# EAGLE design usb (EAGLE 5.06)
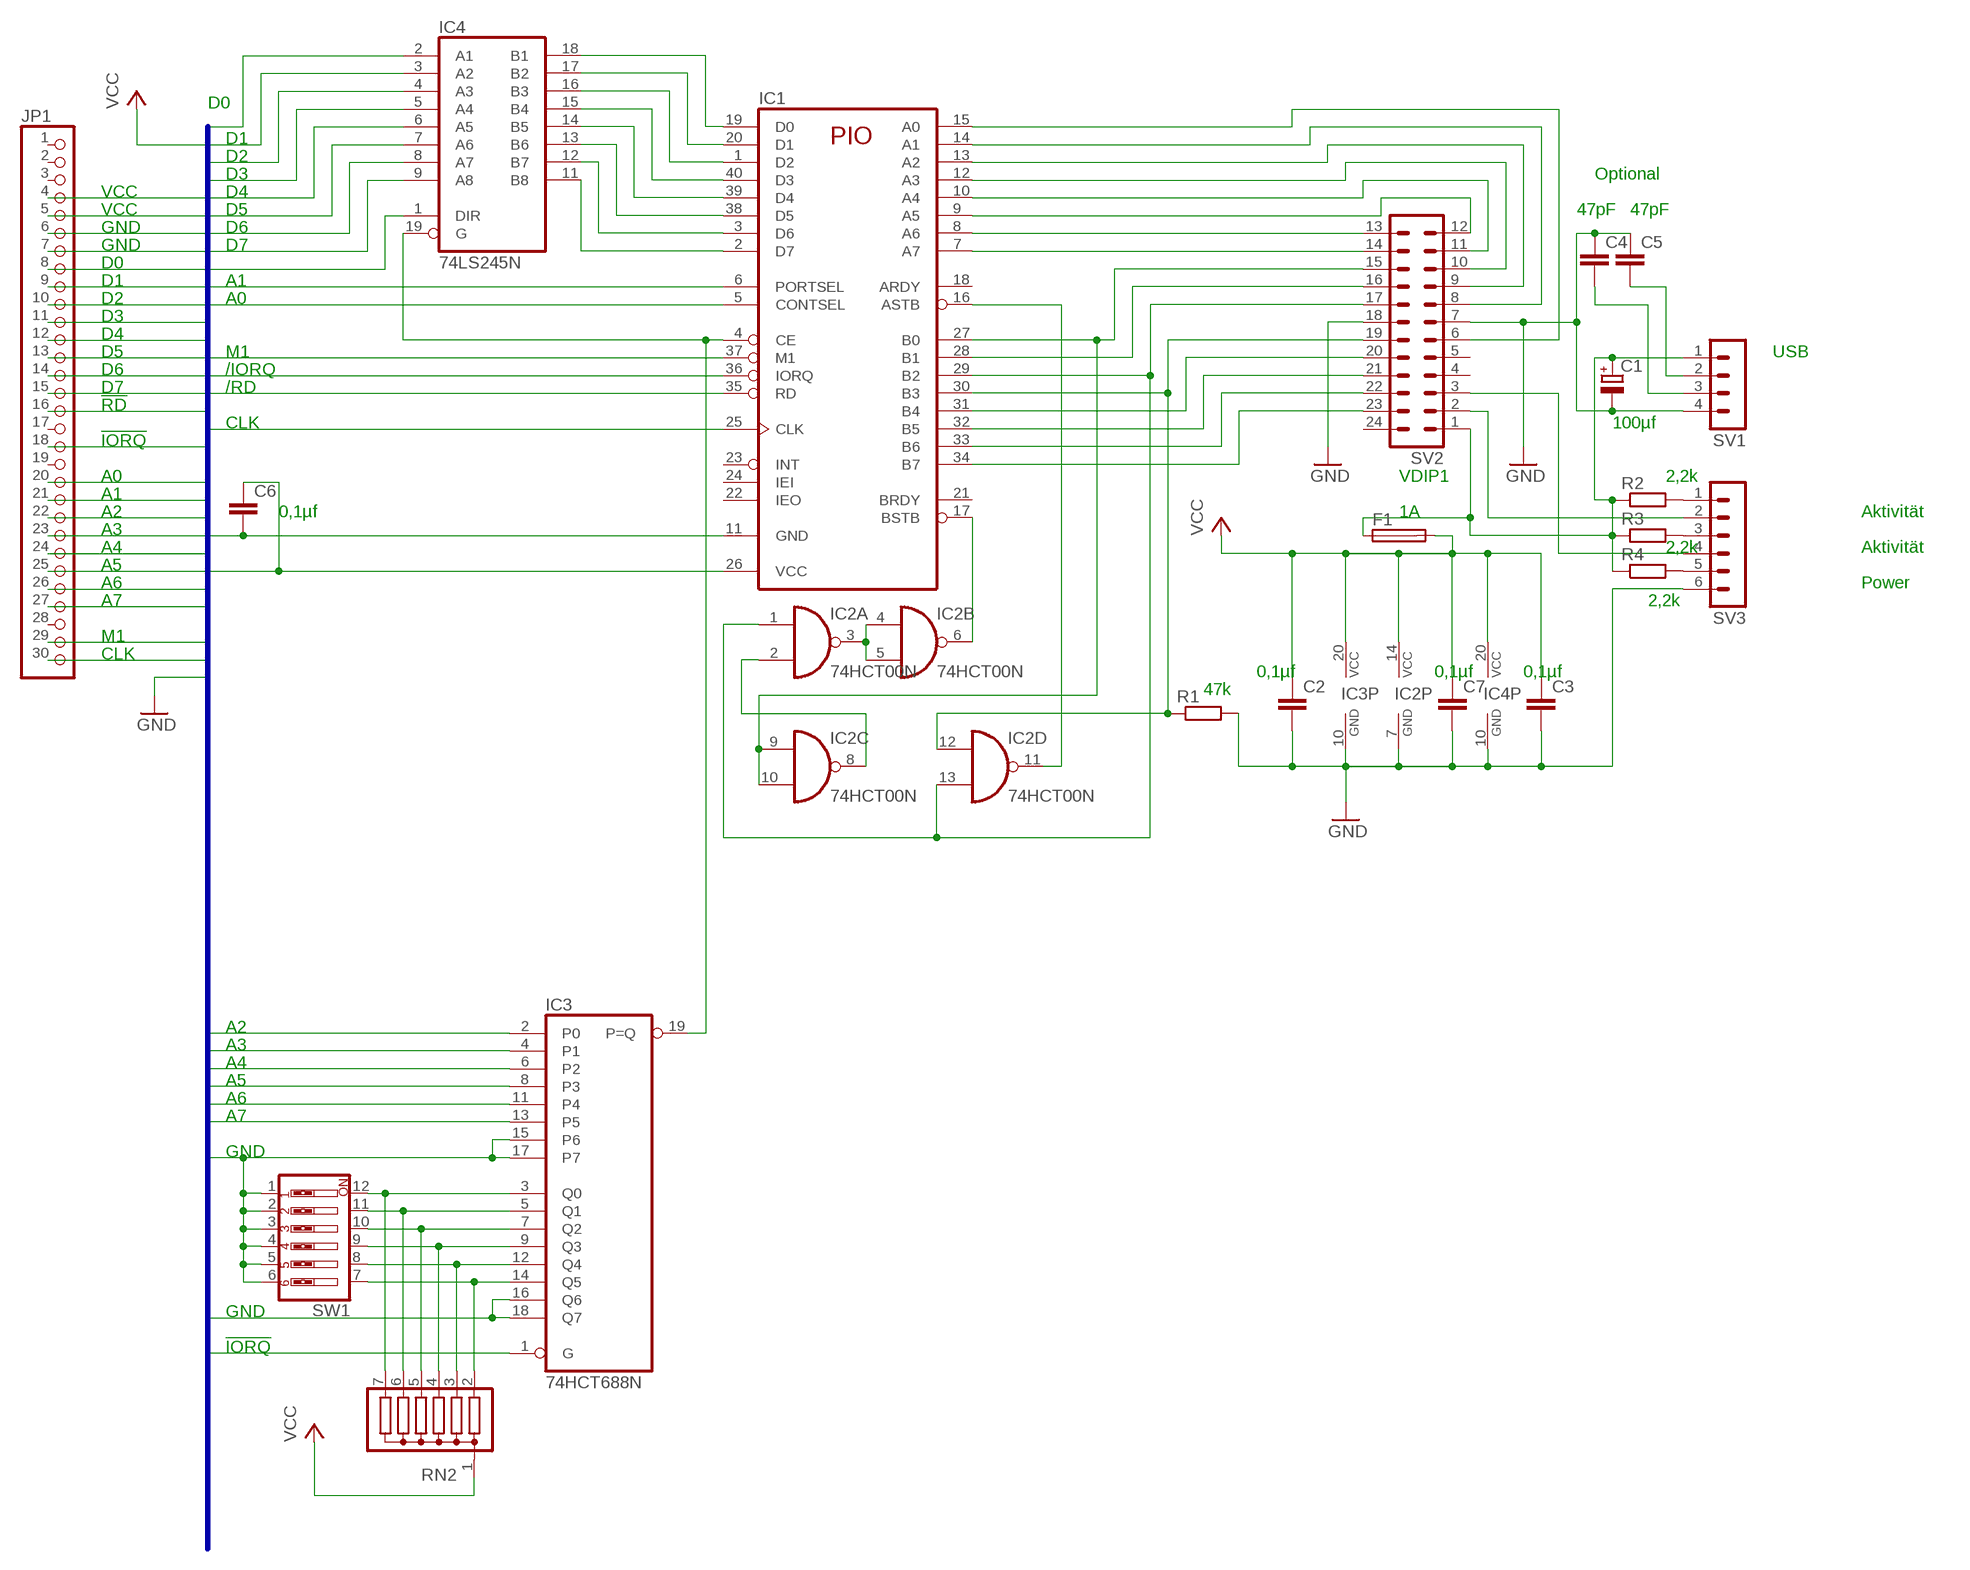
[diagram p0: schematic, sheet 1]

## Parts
C1  CPOL-EUE3.5-10  [E3,5-10]
C2  C-EU025-050X050  [C025-050X050]
C3  C-EU025-050X050  [C025-050X050]
C4  C-EU025-050X050  [C025-050X050]
C5  C-EU025-050X050  [C025-050X050]
C6  C-EU025-050X050  [C025-050X050]
C7  C-EU025-050X050  [C025-050X050]
F1  SH22,5  [SH22,5]
IC1  Z80PIO  [DIL40]
IC2  74HCT00N  [DIL14]
IC3  74HCT688N  [DIL20]
IC4  74LS245N  [DIL20]
JP1  PINHD-1X30  [1X30]
R1  R-EU_0207/15  [0207/15]
R2  R-EU_0207/15  [0207/15]
R3  R-EU_0207/15  [0207/15]
R4  R-EU_0207/15  [0207/15]
RN2  G06R  [SIL7]
SV1  MA04-1  [MA04-1]
SV2  IC24P  [IC24P]
SV3  MA06-1  [MA06-1]
SW1  SW_DIP-6  [EDG-06]

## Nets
!IORQ: IC1.36(IORQ) IC3.1(G) JP1.18
!RD: IC1.35(RD) IC4.1(DIR) JP1.16
A0: IC1.5(CONTSEL) JP1.20
A1: IC1.6(PORTSEL) JP1.21
A2: IC3.2(P0) JP1.22
A3: IC3.4(P1) JP1.23
A4: IC3.6(P2) JP1.24
A5: IC3.8(P3) JP1.25
A6: IC3.11(P4) JP1.26
A7: IC3.13(P5) JP1.27
CLK: IC1.25(CLK) JP1.30
D0: IC4.2(A1) JP1.8
D1: IC4.3(A2) JP1.9
D2: IC4.4(A3) JP1.10
D3: IC4.5(A4) JP1.11
D4: IC4.6(A5) JP1.12
D5: IC4.7(A6) JP1.13
D6: IC4.8(A7) JP1.14
D7: IC4.9(A8) JP1.15
GND [Power]: C1.- C2.2 C3.2 C4.1 C5.1 C6.2 C7.2 IC1.11(GND) IC2.7(P:GND) IC3.10(GND) IC3.15(P6) IC3.16(Q6) IC3.17(P7) IC3.18(Q7) IC4.10(GND) JP1.6 JP1.7 R1.2 SV1.4 SV2.7 SV2.18 SV3.6 SW1.1 SW1.2 SW1.3 SW1.4 SW1.5 SW1.6
M1: IC1.37(M1) JP1.29
N$1: IC1.4(CE) IC3.19(P=Q) IC4.19(G)
N$2: IC3.3(Q0) RN2.7 SW1.12
N$3: IC3.5(Q1) RN2.6 SW1.11
N$4: IC3.7(Q2) RN2.5 SW1.10
N$5: IC3.9(Q3) RN2.4 SW1.9
N$6: IC3.12(Q4) RN2.3 SW1.8
N$7: IC3.14(Q5) RN2.2 SW1.7
N$8: IC1.8(A6) SV2.13
N$9: IC1.9(A5) SV2.12
N$10: IC1.10(A4) SV2.11
N$11: IC1.12(A3) SV2.10
N$12: IC1.13(A2) SV2.9
N$13: IC1.14(A1) SV2.8
N$14: IC1.15(A0) SV2.6
N$15: IC1.7(A7) SV2.14
N$16: IC1.27(B0) IC2.9(C:I0) IC2.10(C:I1) SV2.15
N$17: IC1.28(B1) SV2.16
N$18: R2.2 SV3.1
N$19: IC1.30(B3) IC2.12(D:I0) R1.1 SV2.19
N$20: IC1.31(B4) SV2.20
N$21: IC1.32(B5) SV2.21
N$22: IC1.33(B6) SV2.22
N$23: IC1.34(B7) SV2.23
N$24: IC1.17(BSTB) IC2.6(B:O)
N$25: IC2.3(A:O) IC2.4(B:I0) IC2.5(B:I1)
N$26: IC1.16(ASTB) IC2.11(D:O)
N$27: IC1.29(B2) IC2.1(A:I0) IC2.13(D:I1) SV2.17
N$28: IC2.2(A:I1) IC2.8(C:O)
N$29: R3.2 SV3.3
N$30: R4.2 SV3.5
N$37 [Power]: C1.+ F1.1 R2.1 R3.1 R4.1 SV1.1 SV2.1
N$38: IC1.2(D7) IC4.11(B8)
N$39: SV2.2 SV3.2
N$40: SV2.3 SV3.4
N$41: C5.2 SV1.2
N$42: C4.2 SV1.3
N$43: IC1.3(D6) IC4.12(B7)
N$44: IC1.38(D5) IC4.13(B6)
N$45: IC1.39(D4) IC4.14(B5)
N$46: IC1.40(D3) IC4.15(B4)
N$47: IC1.1(D2) IC4.16(B3)
N$48: IC1.20(D1) IC4.17(B2)
N$49: IC1.19(D0) IC4.18(B1)
VCC [Power]: C2.1 C3.1 C6.1 C7.1 F1.2 IC1.26(VCC) IC2.14(P:VCC) IC3.20(VCC) IC4.20(VCC) JP1.4 JP1.5 RN2.1
Unconnected: IC1.18(ARDY) IC1.21(BRDY) IC1.22(IEO) IC1.23(INT) IC1.24(IEI) JP1.1 JP1.2 JP1.3 JP1.17 JP1.19 JP1.28 SV2.4 SV2.5 SV2.24

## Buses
D[0..7],A[0..7],!WR,!RD,!IORQ,GND,VCC,CLK,M1,RESET,!INT

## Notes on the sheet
- D0
- D1
- D2
- D3 | Optional
- VCC | D4
- VCC | D5 | 47pF | 47pF
- GND | D6
- GND | D7
- D0
- D1 | A1
- D2 | A0
- D3
- D4
- D5 | M1 | USB
- D6 | /IORQ
- D7 | /RD
- !RD
- CLK | 100µf
- !IORQ
- A0 | VDIP1 | 2,2k
- A1
- A2 | 0,1µf | 1A | Aktivität
- A3
- A4 | 2,2k | Aktivität
- A5
- A6 | Power
- A7 | 2,2k
- M1
- CLK
- 0,1µf | 0,1µf | 0,1µf
- 47k
- A2
- A3
- A4
- A5
- A6
- A7
- GND
- GND
- !IORQ

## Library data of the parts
C1 = resistor:CPOL-EU: POLARIZED CAPACITOR, European symbol
C2-C7 = resistor:C-EU: CAPACITOR, European symbol
F1 = fuse:SH22,5: FUSE HOLDER
IC1 = zilog:Z80PIO: Z80 FAMILY DEVICE
IC2 = 74xx-eu:74*00: Quad 2-input NAND gate
IC3 = 74xx-eu:74*688: 8-bit MAGNITUDE/IDENTITY COMPARATOR, totem pole
IC4 = 74xx-eu:74*245: Octal BUS TRANSCEIVER, 3-state
JP1 = pinhead:PINHD-1X30: PIN HEADER
R1-R4 = rcl:R-EU_: RESISTOR, European symbol
RN2 = resistor-sil:G06R: SIL RESISTOR
SV1 = con-lstb:MA04-1: PIN HEADER
SV2 = con-dil:IC24P: DIL CABLE CONNECTOR
SV3 = con-lstb:MA06-1: PIN HEADER
SW1 = special:SW_DIP-6: DIP SWITCH

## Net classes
0 Default: width 0.55 mm, drill 0.4 mm, clearance 0.3 mm
1 Power: width 0.8 mm, drill 0.6 mm, clearance 0.3 mm

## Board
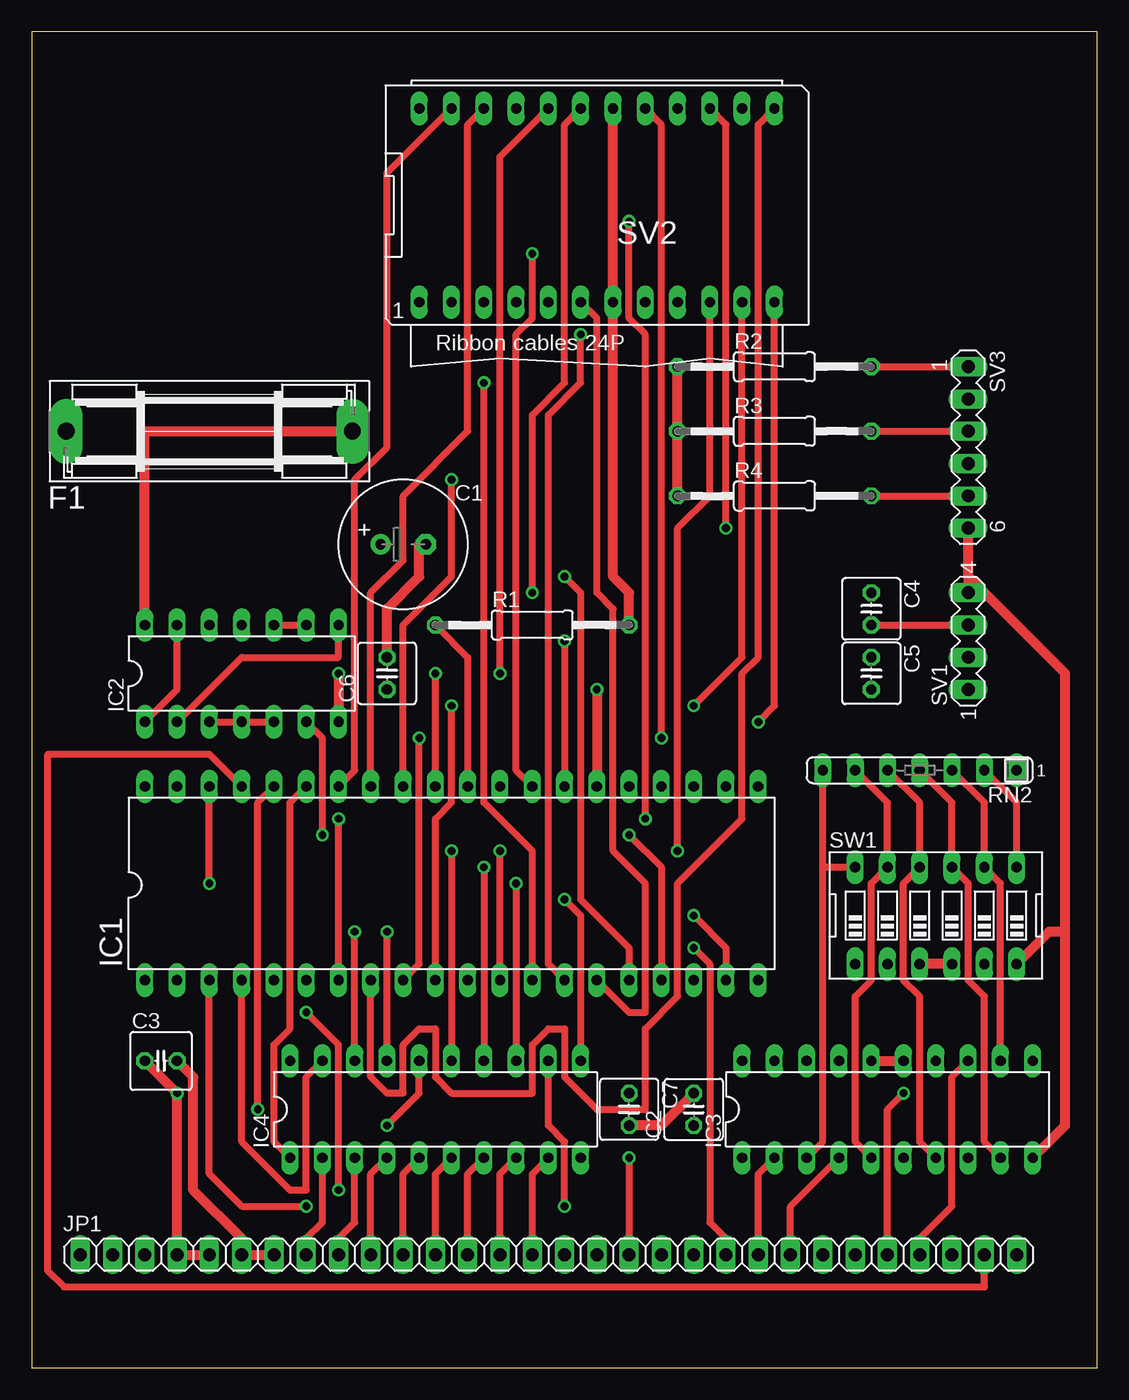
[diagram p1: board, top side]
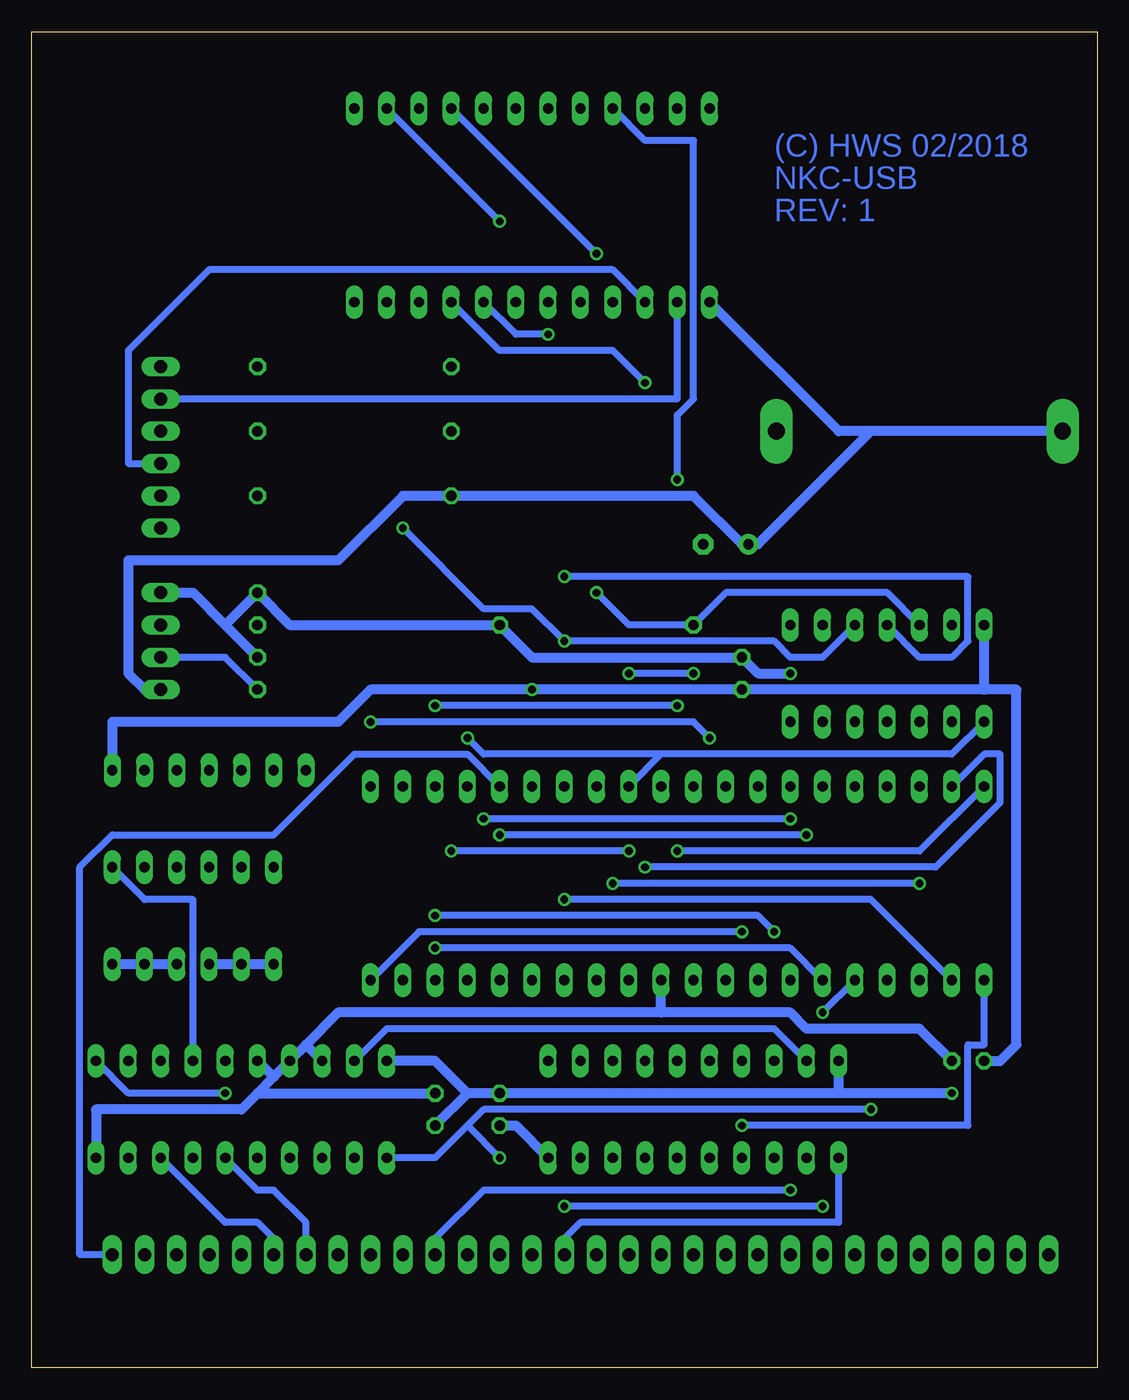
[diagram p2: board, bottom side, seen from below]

Size 83.8 x 105.08 mm. Coordinates in mm from the lower left corner, seen from the top.
Outline: 0,0 83.8,0 83.8,105.08 0,105.08 0,0
Copper layers (1*16): Top 0.035mm / dielectric 1.5mm / Bottom 0.035mm
Design rules "default": minimum track width 10mil, minimum drill 24mil, track to track 8mil, track to pad 8mil, pad to pad 8mil, via to via 8mil, smd to smd 8mil, copper to edge 40mil, drill to drill 8mil, minimum pad ring 10mil, minimum via ring 8mil, stop-mask expansion 4mil, vias tented up to drill 0mil, thermal gap 10mil

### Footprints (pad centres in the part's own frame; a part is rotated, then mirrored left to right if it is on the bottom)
E3,5-10 = drill 0.813 pad 1.6 round: + -1.778,0 | drill 0.813 pad 1.6 octagon: - 1.778,0
C025-050X050 = drill 0.813 octagon: 1 -1.27,0; 2 1.27,0
SH22,5 = drill 1.321 pad 2.54 long: 1 -11.252,0; 2 11.252,0
DIL40 = drill 0.813 long: 1 -24.13,-7.62; 2 -21.59,-7.62; 3 -19.05,-7.62; 4 -16.51,-7.62; 5 -13.97,-7.62; 6 -11.43,-7.62; 7 -8.89,-7.62; 8 -6.35,-7.62; 9 -3.81,-7.62; 10 -1.27,-7.62; 11 1.27,-7.62; 12 3.81,-7.62; 13 6.35,-7.62; 14 8.89,-7.62; 15 11.43,-7.62; 16 13.97,-7.62; 17 16.51,-7.62; 18 19.05,-7.62; 19 21.59,-7.62; 20 24.13,-7.62; 21 24.13,7.62; 22 21.59,7.62; 23 19.05,7.62; 24 16.51,7.62; 25 13.97,7.62; 26 11.43,7.62; 27 8.89,7.62; 28 6.35,7.62; 29 3.81,7.62; 30 1.27,7.62; 31 -1.27,7.62; 32 -3.81,7.62; 33 -6.35,7.62; 34 -8.89,7.62; 35 -11.43,7.62; 36 -13.97,7.62; 37 -16.51,7.62; 38 -19.05,7.62; 39 -21.59,7.62; 40 -24.13,7.62
DIL14 = drill 0.813 long: 1 -7.62,-3.81; 2 -5.08,-3.81; 3 -2.54,-3.81; 4 0,-3.81; 5 2.54,-3.81; 6 5.08,-3.81; 7 7.62,-3.81; 8 7.62,3.81; 9 5.08,3.81; 10 2.54,3.81; 11 0,3.81; 12 -2.54,3.81; 13 -5.08,3.81; 14 -7.62,3.81
DIL20 = drill 0.813 long: 1 -11.43,-3.81; 2 -8.89,-3.81; 3 -6.35,-3.81; 4 -3.81,-3.81; 5 -1.27,-3.81; 6 1.27,-3.81; 7 3.81,-3.81; 8 6.35,-3.81; 9 8.89,-3.81; 10 11.43,-3.81; 11 11.43,3.81; 12 8.89,3.81; 13 6.35,3.81; 14 3.81,3.81; 15 1.27,3.81; 16 -1.27,3.81; 17 -3.81,3.81; 18 -6.35,3.81; 19 -8.89,3.81; 20 -11.43,3.81
1X30 = drill 1.016 long: 1 -36.83,0; 2 -34.29,0; 3 -31.75,0; 4 -29.21,0; 5 -26.67,0; 6 -24.13,0; 7 -21.59,0; 8 -19.05,0; 9 -16.51,0; 10 -13.97,0; 11 -11.43,0; 12 -8.89,0; 13 -6.35,0; 14 -3.81,0; 15 -1.27,0; 16 1.27,0; 17 3.81,0; 18 6.35,0; 19 8.89,0; 20 11.43,0; 21 13.97,0; 22 16.51,0; 23 19.05,0; 24 21.59,0; 25 24.13,0; 26 26.67,0; 27 29.21,0; 28 31.75,0; 29 34.29,0; 30 36.83,0
0207/15 = drill 0.813 octagon: 1 -7.62,0; 2 7.62,0
SIL7 = drill 0.813 long: 1 -7.62,0; 2 -5.08,0; 3 -2.54,0; 4 0,0; 5 2.54,0; 6 5.08,0; 7 7.62,0
MA04-1 = drill 1.016 long: 1 -3.81,0; 2 -1.27,0; 3 1.27,0; 4 3.81,0
IC24P = drill 0.813 long: 1 -13.97,-7.62; 2 -11.43,-7.62; 3 -8.89,-7.62; 4 -6.35,-7.62; 5 -3.81,-7.62; 6 -1.27,-7.62; 7 1.27,-7.62; 8 3.81,-7.62; 9 6.35,-7.62; 10 8.89,-7.62; 11 11.43,-7.62; 12 13.97,-7.62; 13 13.97,7.62; 14 11.43,7.62; 15 8.89,7.62; 16 6.35,7.62; 17 3.81,7.62; 18 1.27,7.62; 19 -1.27,7.62; 20 -3.81,7.62; 21 -6.35,7.62; 22 -8.89,7.62; 23 -11.43,7.62; 24 -13.97,7.62
MA06-1 = drill 1.016 long: 1 -6.35,0; 2 -3.81,0; 3 -1.27,0; 4 1.27,0; 5 3.81,0; 6 6.35,0
EDG-06 = drill 0.813 long: 1 -6.35,-3.81; 2 -3.81,-3.81; 3 -1.27,-3.81; 4 1.27,-3.81; 5 3.81,-3.81; 6 6.35,-3.81; 7 6.35,3.81; 8 3.81,3.81; 9 1.27,3.81; 10 -1.27,3.81; 11 -3.81,3.81; 12 -6.35,3.81

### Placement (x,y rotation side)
C1  29.21,64.77 0 top
C2  52.07,20.32 90 top
C3  10.16,24.13 0 top
C4  66.04,59.69 270 top
C5  66.04,54.61 270 top
C6  27.94,54.61 90 top
C7  46.99,20.32 270 top
F1  13.97,73.66 0 top
IC1  33.02,38.1 0 top
IC2  16.51,54.61 0 top
IC3  67.31,20.32 0 top
IC4  31.75,20.32 0 top
JP1  40.64,8.89 0 top
R1  39.37,58.42 0 top
R2  58.42,78.74 0 top
R3  58.42,73.66 0 top
R4  58.42,68.58 0 top
RN2  69.85,46.99 180 top
SV1  73.66,57.15 90 top
SV2  44.45,91.44 0 top
SV3  73.66,72.39 270 top
SW1  71.12,35.56 0 top

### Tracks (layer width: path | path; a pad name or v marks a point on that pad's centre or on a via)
!IORQ  (via drill 0.61)
  Top 0.55: IC1.36 17.78,44.45 v17.78,20.32 | v46.99,16.51 JP1.18
  Bottom 0.55: v17.78,20.32 48.26,20.32 49.53,19.05 | 49.53,19.05 52.07,16.51 IC3.1 | 49.53,19.05 v46.99,16.51
!RD
  Top 0.55: IC1.35 20.32,44.45 20.32,26.67 19.05,25.4 19.05,17.78 IC4.1
  Bottom 0.55: IC4.1 20.32,11.43 40.64,11.43 41.91,10.16 JP1.16
A0  (via drill 0.61)
  Top 0.55: v21.59,27.94 24.13,25.4 v24.13,13.97
  Bottom 0.55: v21.59,27.94 IC1.5 | v24.13,13.97 48.26,13.97 52.07,10.16 JP1.20
A1  (via drill 0.61)
  Top 0.55: v52.07,33.02 53.34,31.75 53.34,11.43 54.61,10.16 JP1.21
  Bottom 0.55: IC1.6 24.13,33.02 v52.07,33.02
A2
  Top 0.55: IC3.2 57.15,15.24 JP1.22
A3
  Top 0.55: IC3.4 59.69,12.7 JP1.23
A4
  Bottom 0.55: IC3.6 66.04,13.97 64.77,13.97 62.23,11.43 JP1.24
A5
  Bottom 0.55: IC3.8 68.58,11.43 66.04,11.43 64.77,10.16 JP1.25
A6  (via drill 0.61)
  Top 0.55: v68.58,21.59 67.31,20.32 JP1.26
  Bottom 0.55: IC3.11 76.2,21.59 v68.58,21.59
A7
  Top 0.55: IC3.13 72.39,22.86 72.39,12.7 69.85,10.16 JP1.27
CLK
  Bottom 0.55: IC1.25 49.53,48.26 58.42,48.26 64.77,41.91 77.47,41.91 80.01,39.37 80.01,8.89 JP1.30
D0
  Top 0.55: IC4.2 22.86,11.43 21.59,10.16 JP1.8
D1
  Top 0.55: IC4.3 25.4,11.43 24.13,10.16 JP1.9
D2
  Top 0.55: IC4.4 26.67,15.24 JP1.10
D3
  Top 0.55: IC4.5 29.21,15.24 JP1.11
D4
  Top 0.55: IC4.6 31.75,15.24 JP1.12
D5
  Top 0.55: IC4.7 34.29,15.24 JP1.13
D6
  Top 0.55: IC4.8 36.83,15.24 JP1.14
D7
  Top 0.55: IC4.9 39.37,15.24 JP1.15
GND  (via drill 0.61)
  Top 0.8: C3.2 12.7,22.86 12.7,13.97 16.51,10.16 JP1.6 JP1.7 | C2.2 49.53,19.05 C7.2 | IC3.16 IC3.15 | 73.66,62.23 SV1.4 | 73.66,62.23 SV3.6 | SV2.18 SV2.7 45.72,62.23 46.99,60.96 R1.2 | v24.13,54.61 IC2.7 | C6.2 27.94,59.69 30.48,62.23 30.48,64.77 C1.- | IC3.10 81.28,19.05 81.28,34.29 | 81.28,34.29 81.28,54.61 73.66,62.23 | SW1.4 SW1.3 | SW1.6 80.01,34.29 81.28,34.29
  Bottom 0.8: IC4.10 45.72,19.05 C7.2 | 34.29,27.94 IC1.11 | 34.29,27.94 59.69,27.94 62.23,25.4 | 62.23,25.4 IC3.17 64.77,22.86 | 62.23,25.4 IC3.18 | IC3.10 78.74,20.32 67.31,20.32 66.04,21.59 | 64.77,22.86 66.04,21.59 | 64.77,22.86 IC3.16 | 66.04,21.59 C2.2 | C3.2 13.97,26.67 22.86,26.67 24.13,27.94 34.29,27.94 | 68.58,58.42 71.12,60.96 SV1.4 | 68.58,58.42 C5.1 | 68.58,58.42 C4.1 63.5,58.42 R1.2 44.45,55.88 C6.2 26.67,54.61 v24.13,54.61 | SW1.4 SW1.5 SW1.6 | SW1.3 SW1.2 SW1.1
M1
  Top 0.55: IC1.37 13.97,48.26 1.27,48.26 1.27,7.62 2.54,6.35 74.93,6.35 JP1.29
N$1
  Top 0.55: IC1.4 16.51,17.78 20.32,13.97 21.59,13.97 21.59,22.86 IC4.19
  Bottom 0.55: IC4.19 25.4,26.67 55.88,26.67 IC3.19
N$2
  Top 0.55: IC3.3 62.23,17.78 62.23,39.37 | 62.23,39.37 RN2.7 | 62.23,39.37 SW1.12
N$3
  Top 0.55: IC3.5 64.77,17.78 64.77,29.21 66.04,30.48 66.04,38.1 SW1.11 67.31,44.45 RN2.6
N$4
  Top 0.55: IC3.7 69.85,17.78 69.85,29.21 68.58,30.48 68.58,38.1 SW1.10 69.85,44.45 RN2.5
N$5
  Top 0.55: IC3.9 74.93,17.78 74.93,29.21 73.66,30.48 73.66,38.1 SW1.9 72.39,44.45 RN2.4
N$6
  Top 0.55: IC3.12 76.2,38.1 SW1.8 74.93,44.45 RN2.3
N$7
  Top 0.55: RN2.2 77.47,44.45 SW1.7
  Bottom 0.55: IC3.14 71.12,36.83 74.93,36.83 SW1.7
N$8
  Top 0.55: IC1.8 26.67,22.86 27.94,21.59 29.21,21.59 29.21,25.4 30.48,26.67 31.75,26.67 31.75,22.86 33.02,21.59 39.37,21.59 39.37,25.4 40.64,26.67 41.91,26.67 41.91,22.86 44.45,20.32 48.26,20.32 48.26,26.67 50.8,29.21 50.8,38.1 55.88,43.18 55.88,54.61 57.15,55.88 57.15,97.79 SV2.13
N$9  (via drill 0.61)
  Top 0.55: IC1.9 30.48,31.75 v30.48,49.53 | v57.15,50.8 58.42,52.07 SV2.12
  Bottom 0.55: v30.48,49.53 31.75,50.8 v57.15,50.8
N$10  (via drill 0.61)
  Top 0.55: IC1.10 31.75,43.18 33.02,44.45 v33.02,52.07 | v52.07,52.07 55.88,55.88 SV2.11
  Bottom 0.55: v33.02,52.07 v52.07,52.07
N$11  (via drill 0.61)
  Top 0.55: IC1.12 v36.83,40.64 | v50.8,40.64 50.8,66.04 53.34,68.58 SV2.10
  Bottom 0.55: v36.83,40.64 v50.8,40.64
N$12  (via drill 0.61)
  Top 0.55: IC1.13 39.37,40.64 35.56,44.45 v35.56,77.47
  Bottom 0.55: v35.56,77.47 38.1,80.01 46.99,80.01 SV2.9
N$13  (via drill 0.61)
  Top 0.55: IC1.14 40.64,31.75 40.64,74.93 43.18,77.47 v43.18,81.28
  Bottom 0.55: v43.18,81.28 45.72,81.28 SV2.8
N$14
  Top 0.55: IC1.15 46.99,27.94 48.26,27.94 48.26,38.1 45.72,40.64 45.72,59.69 44.45,60.96 44.45,82.55 SV2.6
N$15  (via drill 0.61)
  Top 0.55: IC1.7 v24.13,43.18 | v48.26,43.18 48.26,81.28 46.99,82.55 v46.99,90.17
  Bottom 0.55: v24.13,43.18 v48.26,43.18 | v46.99,90.17 SV2.14
N$16  (via drill 0.61)
  Top 0.55: IC2.10 IC2.9 | v41.91,57.15 IC1.27 | SV2.15 54.61,97.79 v54.61,66.04
  Bottom 0.55: IC2.10 21.59,55.88 24.13,55.88 25.4,57.15 v41.91,57.15 44.45,59.69 48.26,59.69 v54.61,66.04
N$17  (via drill 0.61)
  Top 0.55: IC1.28 38.1,46.99 38.1,81.28 39.37,82.55 v39.37,87.63
  Bottom 0.55: v39.37,87.63 SV2.16
N$18
  Top 0.55: R2.2 SV3.1
N$19  (via drill 0.61)
  Top 0.55: IC1.30 34.29,55.88 R1.1 | SV2.19 41.91,97.79 41.91,77.47 39.37,74.93 v39.37,60.96
  Bottom 0.55: IC2.12 16.51,60.96 29.21,60.96 R1.1 36.83,58.42 v39.37,60.96
N$20  (via drill 0.61)
  Top 0.55: IC1.31 v31.75,54.61 | v36.83,54.61 36.83,95.25 SV2.20
  Bottom 0.55: v31.75,54.61 v36.83,54.61
N$21  (via drill 0.61)
  Top 0.55: IC1.32 29.21,58.42 33.02,62.23 v33.02,69.85
  Bottom 0.55: v33.02,69.85 33.02,74.93 31.75,76.2 31.75,96.52 35.56,96.52 SV2.21
N$22
  Top 0.55: IC1.33 26.67,60.96 29.21,63.5 29.21,68.58 34.29,73.66 34.29,97.79 SV2.22
N$23
  Top 0.55: IC1.34 25.4,46.99 25.4,69.85 27.94,72.39 27.94,93.98 SV2.23
N$24  (via drill 0.61)
  Top 0.55: IC2.6 22.86,49.53 v22.86,41.91 | v46.99,41.91 49.53,39.37 IC1.17
  Bottom 0.55: v22.86,41.91 v46.99,41.91
N$25
  Top 0.55: IC2.3 IC2.4 IC2.5
N$26  (via drill 0.61)
  Top 0.55: v41.91,62.23 43.18,60.96 43.18,36.83 46.99,33.02 IC1.16
  Bottom 0.55: IC2.11 13.97,55.88 11.43,55.88 10.16,57.15 10.16,62.23 v41.91,62.23
N$27  (via drill 0.61)
  Top 0.55: IC2.1 11.43,53.34 IC2.13 | SV2.17 49.53,97.79 v49.53,49.53
  Bottom 0.55: 34.29,48.26 IC1.29 | 34.29,48.26 11.43,48.26 IC2.1 | v49.53,49.53 48.26,48.26 34.29,48.26
N$28
  Top 0.55: IC2.2 16.51,55.88 24.13,55.88 IC2.8
N$29
  Top 0.55: R3.2 SV3.3
N$30
  Top 0.55: R4.2 SV3.5
N$37
  Top 0.8: R4.1 R3.1 R2.1
  Bottom 0.8: SV2.1 20.32,73.66 17.78,73.66 | F1.1 17.78,73.66 | 17.78,73.66 26.67,64.77 C1.+ 27.94,64.77 31.75,68.58 R4.1 54.61,68.58 59.69,63.5 76.2,63.5 76.2,54.61 74.93,53.34 SV1.1
N$38  (via drill 0.61)
  Top 0.55: v41.91,36.83 43.18,35.56 IC4.11
  Bottom 0.55: IC1.2 17.78,36.83 v41.91,36.83
N$39
  Bottom 0.55: SV2.2 33.02,76.2 SV3.2
N$40
  Bottom 0.55: SV2.3 38.1,86.36 69.85,86.36 76.2,80.01 76.2,71.12 SV3.4
N$41
  Bottom 0.55: C5.2 68.58,55.88 SV1.2
N$42
  Top 0.55: C4.2 SV1.3
N$43  (via drill 0.61)
  Top 0.55: IC4.12 40.64,19.05 41.91,17.78 v41.91,12.7 | v21.59,12.7 16.51,12.7 13.97,15.24 IC1.3
  Bottom 0.55: v21.59,12.7 v41.91,12.7
N$44  (via drill 0.61)
  Top 0.55: v38.1,38.1 IC4.13 | v13.97,38.1 IC1.38
  Bottom 0.55: v13.97,38.1 v38.1,38.1
N$45  (via drill 0.61)
  Top 0.55: v35.56,39.37 IC4.14
  Bottom 0.55: v35.56,39.37 12.7,39.37 7.62,44.45 7.62,48.26 8.89,48.26 IC1.39
N$46  (via drill 0.61)
  Top 0.55: v33.02,40.64 IC4.15
  Bottom 0.55: v33.02,40.64 13.97,40.64 IC1.40
N$47  (via drill 0.61)
  Top 0.55: v27.94,19.05 30.48,21.59 IC4.16
  Bottom 0.55: IC1.1 8.89,25.4 10.16,25.4 10.16,19.05 v27.94,19.05
N$48  (via drill 0.61)
  Top 0.55: IC4.17 v27.94,34.29
  Bottom 0.55: v27.94,34.29 53.34,34.29 IC1.20
N$49  (via drill 0.61)
  Top 0.55: IC4.18 v25.4,34.29 | v52.07,35.56 54.61,33.02 IC1.19
  Bottom 0.55: v25.4,34.29 26.67,35.56 v52.07,35.56
VCC  (via drill 0.61)
  Top 0.8: C3.1 v11.43,21.59 JP1.4 JP1.5 | v44.45,53.34 IC1.26 | IC2.14 8.89,73.66 F1.2
  Bottom 0.8: 20.32,21.59 IC4.20 | 20.32,21.59 C7.1 49.53,21.59 | 49.53,21.59 C2.1 | IC3.20 52.07,24.13 49.53,21.59 | 8.89,53.34 IC2.14 | 8.89,53.34 C6.1 v44.45,53.34 57.15,53.34 59.69,50.8 77.47,50.8 RN2.1 | C3.1 7.62,24.13 6.35,25.4 6.35,53.34 8.89,53.34 | v11.43,21.59 20.32,21.59

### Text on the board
Bottom: (C) HWS 02/2018 | NKC-USB | REV: 1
